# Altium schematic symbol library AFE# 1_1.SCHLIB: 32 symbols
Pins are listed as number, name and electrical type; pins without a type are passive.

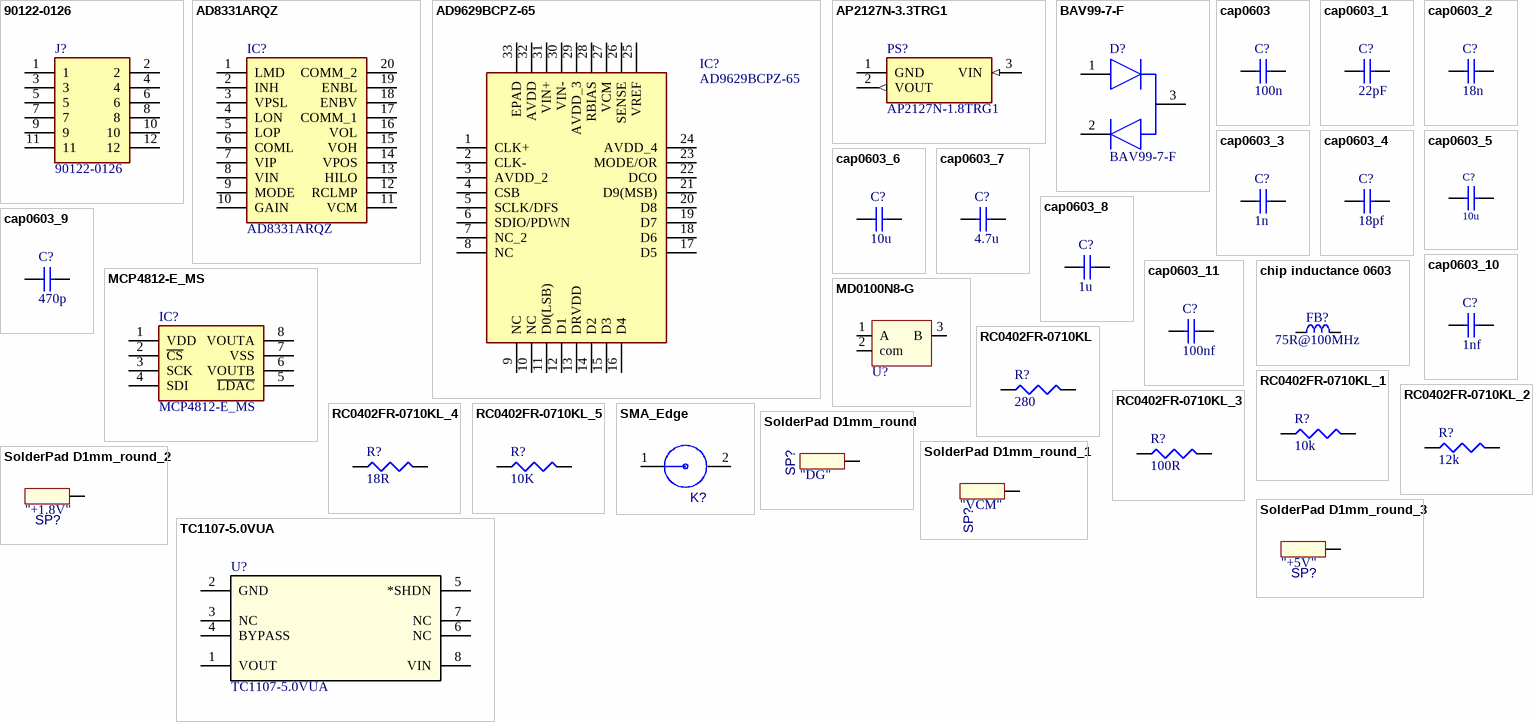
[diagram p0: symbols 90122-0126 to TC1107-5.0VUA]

## 90122-0126
designator J?
Connector; Manufacturer_Name: Molex
footprint HDRRA12W65P254_2X6_1516X250X615P
pins: 1, 2, 3, 4, 5, 6, 7, 8, 9, 10, 11, 12

## AD8331ARQZ
designator IC?
Integrated Circuit; Manufacturer_Name: Analog Devices
footprint SOP64P600X175-20N
pins: 1 LMD, 2 INH, 3 VPSL, 4 LON, 5 LOP, 6 COML, 7 VIP, 8 VIN, 9 MODE, 10 GAIN, 11 VCM, 12 RCLMP, 13 HILO, 14 VPOS, 15 VOH, 16 VOL, 17 COMM_1, 18 ENBV, 19 ENBL, 20 COMM_2

## AD9629BCPZ-65
designator IC?
Integrated Circuit; Manufacturer_Name: Analog Devices
footprint QFN50P500X500X100-33N
pins: 1 CLK+, 2 CLK-, 3 AVDD_2, 4 CSB, 5 SCLK/DFS, 6 SDIO/PDWN, 7 NC_2, 8 NC, 9 NC, 10 NC, 11 D0(LSB), 12 D1, 13 DRVDD, 14 D2, 15 D3, 16 D4, 17 D5, 18 D6, 19 D7, 20 D8, 21 D9(MSB), 22 DCO, 23 MODE/OR, 24 AVDD_4, 25 VREF, 26 SENSE, 27 VCM, 28 RBIAS, 29 AVDD_3, 30 VIN-, 31 VIN+, 32 AVDD, 33 EPAD

## AP2127N-3.3TRG1
designator PS?, comment AP2127N-1.8TRG1
Power Supply; Manufacturer_Name: Diodes Inc.; Manufacturer_Part_Number: AP2127N-3.3TRG1
footprint SOT89P240X110-3N
footprint SOT89P240X110-3N
pins: 1 GND (power), 2 VOUT (out), 3 VIN (in)

## BAV99-7-F
designator D?
Diode; Manufacturer_Name: Diodes Inc.
footprint SOT95P240X120-3N
footprint SOT95P240X120-3N
pins: 1 ANODE, 2 CATHODE, 3 A/K

## cap0603
designator C?, comment value 100n  (hidden comment: cap0402)
Capacitor  0402 inch
signal-integrity model Cap
footprint SM0603 _3D_cap (standard  0603 inch size)
footprint 0402_C
pins: 1, 2

## cap0603_1
designator C?, comment value 22pF  (hidden comment: cap0402)
Capacitor  0402 inch
signal-integrity model Cap
footprint SM0603 _3D_cap (standard  0603 inch size)
footprint 0402_C
pins: 1, 2

## cap0603_2
designator C?, comment value 18n  (hidden comment: cap0402)
Capacitor  0402 inch
signal-integrity model Cap
footprint SM0603 _3D_cap (standard  0603 inch size)
footprint 0402_C
pins: 1, 2

## cap0603_3
designator C?, comment value 1n  (hidden comment: cap0402)
Capacitor  0402 inch
signal-integrity model Cap
footprint SM0603 _3D_cap (standard  0603 inch size)
footprint 0402_C
pins: 1, 2

## cap0603_4
designator C?, comment value 18pf  (hidden comment: cap0402)
Capacitor  0402 inch
signal-integrity model Cap
footprint SM0603 _3D_cap (standard  0603 inch size)
footprint 0402_C
pins: 1, 2

## cap0603_5
designator C?, comment value 10u  (hidden comment: cap0402)
Capacitor  0402 inch
signal-integrity model Cap
footprint SM0603 _3D_cap
pins: 1, 2

## cap0603_6
designator C?, comment value 10u  (hidden comment: cap0603)
Capacitor  0603 inch
signal-integrity model Cap
footprint SM0603 _3D_cap (standard  0603 inch size)
footprint SM0603 _3D_cap
pins: 1, 2

## cap0603_7
designator C?, comment value 4.7u  (hidden comment: cap0603)
Capacitor  0603 inch
signal-integrity model Cap
footprint SM0603 _3D_cap (standard  0603 inch size)
footprint SM0603 _3D_cap
pins: 1, 2

## cap0603_8
designator C?, comment value 1u  (hidden comment: cap0603)
Capacitor  0603 inch
signal-integrity model Cap
footprint SM0603 _3D_cap (standard  0603 inch size)
footprint SM0603 _3D_cap
pins: 1, 2

## cap0603_9
designator C?, comment value 470p  (hidden comment: cap0402)
Capacitor  0402 inch
signal-integrity model Cap
footprint SM0603 _3D_cap (standard  0603 inch size)
footprint 0402_C
pins: 1, 2

## cap0603_10
designator C?, comment value 1nf  (hidden comment: cap0402)
Capacitor  0603 inch
signal-integrity model Cap
footprint SM0603 _3D_cap (standard  0603 inch size)
footprint 0402_C
pins: 1, 2

## cap0603_11
designator C?, comment value 100nf  (hidden comment: cap0402)
Capacitor  0402 inch
signal-integrity model Cap
footprint SM0603 _3D_cap (standard  0603 inch size)
footprint 0402_C
pins: 1, 2

## chip inductance 0603
designator FB?, comment 75R@100MHz
chip inductance 0603; Part Number: IND0805_MURATA_BLM21BB750SN1D; Part Description: SMD EMIFIL Suppression Chip Ferrite Bead; Manufacturer: MURATA; Manufacturer Part Number: BLM21BB750SN1D; Power: 700mA; Resistance: 0.16R; Tolerance: ±25%; Table: Inductors SMD
footprint SM0603_3D_res (0603 inch resistor)
pins: 1, 2

## MCP4812-E_MS
designator IC?
Integrated Circuit; Manufacturer_Name: Microchip; Manufacturer_Part_Number: MCP4812-E/MS
footprint SOP65P490X110-8N
pins: 1 VDD, 2 ~{CS}, 3 SCK, 4 SDI, 5 ~{LDAC}, 6 VOUTB, 7 VSS, 8 VOUTA

## MD0100N8-G
designator U?, comment T/R switch  (value not drawn)
footprint SOT89-150P409X160-3N (SOT89, 3-Leads, Body 4,50x2,45mm, Pitch 1,50mm, Lead Span 4,1mm, IPC Medium Density)
pins: 1 A, 2 com, 3 B

## RC0402FR-0710KL
designator R?, comment 280
RES 280 OHM 1/16W 0402 SMD; Power (Watts): 0.063W, 1/16W; .Checked PCB: used
footprint R0402
footprint 0402_R
pins: 1, 2

## RC0402FR-0710KL_1
designator R?, comment 10k
RES 10K OHM 1/16W 1% 0402 SMD; Resistance (Ohms): 280; Power (Watts): 0.063W, 1/16W; .Checked PCB: used
footprint R0402
footprint 0402_R
pins: 1, 2

## RC0402FR-0710KL_2
designator R?, comment 12k
RES 12K OHM 1/16W 0402 SMD; Power (Watts): 0.063W, 1/16W; .Checked PCB: used
footprint R0402
footprint 0402_R
pins: 1, 2

## RC0402FR-0710KL_3
designator R?, comment 100R
RES 10K OHM 1/16W 0402 SMD; Power (Watts): 0.063W, 1/16W; .Checked PCB: used
footprint R0402
footprint 0402_R
pins: 1, 2

## RC0402FR-0710KL_4
designator R?, comment 18R
RES 18 OHM 1/16W 0402 SMD; Power (Watts): 0.063W, 1/16W; .Checked PCB: used
footprint R0402
footprint 0402_R
footprint 0402_R
pins: 1, 2

## RC0402FR-0710KL_5
designator R?, comment 10K
RES 10K OHM 1/16W 0402 SMD; Power (Watts): 0.063W, 1/16W; .Checked PCB: used
footprint R0402
footprint 0402_R
pins: 1, 2

## SMA_Edge
designator K?  (value not drawn)
footprint AMPHENOL_132357-11
footprint AMPHENOL_132357-11
pins: 1, 2

## SolderPad D1mm_round
designator SP?  value "DG"  (hidden comment: SolderPad D1mm_round)
for finger touch
footprint SolderPad_D1mm _round
pins: 1

## SolderPad D1mm_round_1
designator SP?, comment value "VCM"  (hidden comment: SolderPad D1mm_round)
for finger touch
footprint SolderPad_D1mm _round (7mm solder circle for finger touch)
footprint SolderPad_D1mm _round
pins: 1

## SolderPad D1mm_round_2
designator SP?, comment value "+1.8V"  (hidden comment: SolderPad D1mm_round)
for finger touch
footprint SolderPad_D1mm _round
pins: 1

## SolderPad D1mm_round_3
designator SP?, comment value "+5V"  (hidden comment: SolderPad D1mm_round)
for finger touch
footprint SolderPad_D1mm _round
pins: 1

## TC1107-5.0VUA
designator U?
No Description Available; Mfr_Name: Microchip
footprint MSOP8_MC_MCH
footprint MSOP8_MC_MCH_
pins: 1 VOUT, 2 GND, 3 NC, 4 BYPASS, 5 *SHDN, 6 NC, 7 NC, 8 VIN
